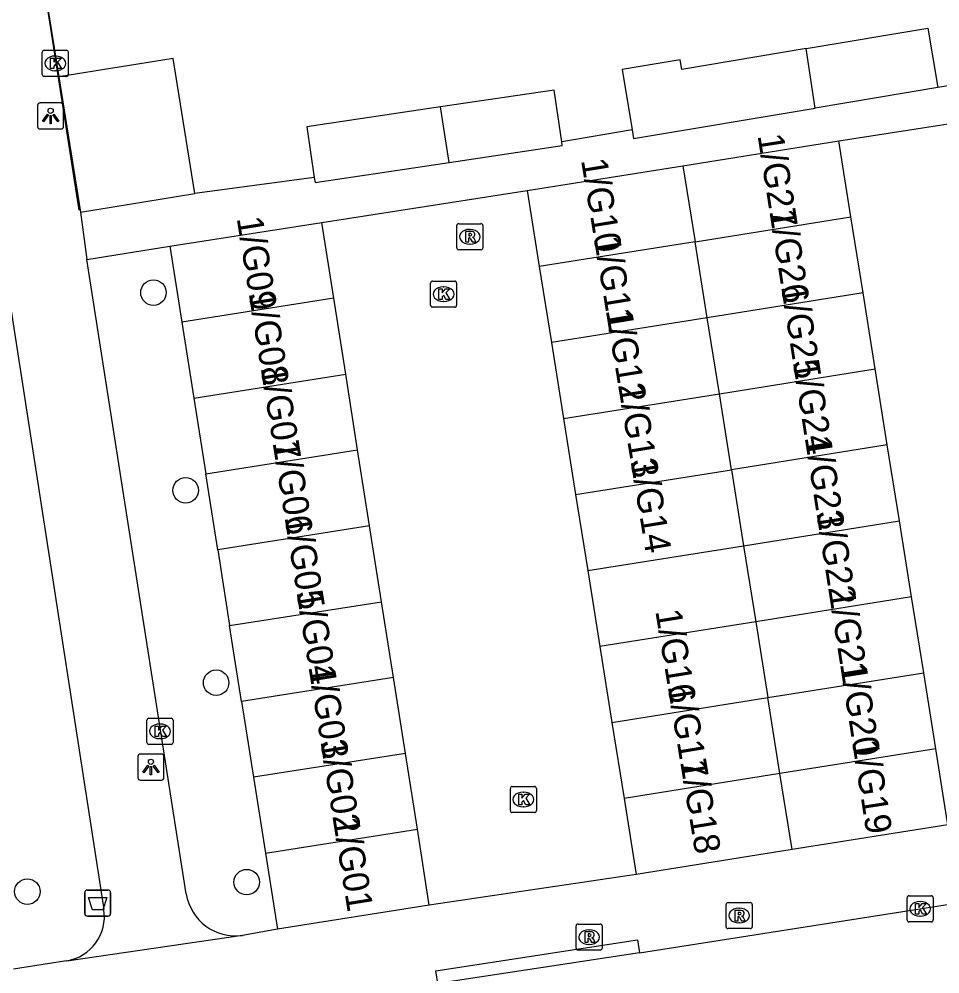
# Model space of a CAD drawing. Extents: x 160077 to 160945, y 386481 to 387498.
# Drawn here: x 160454.89 to 160490.18, y 387076.44 to 387113.04 of the extents above; entities that cross this region are included whole.
import ezdxf

# ---------------------------------------------------------------- set-up
doc = ezdxf.new("R2010")
doc.units = 0
for name, color, linetype in [('IMGEO_Afvalbak', 7, 'Continuous'), ('IMGEO_Boom', 7, 'Continuous'), ('IMGEO_Kolk', 7, 'Continuous'), ('IMGEO_Lichtpunt', 7, 'Continuous'), ('IMGEO_Muur', 7, 'Continuous'), ('IMGEO_Pand', 7, 'Continuous'), ('IMGEO_Pand_nummerreeks', 7, 'Continuous'), ('IMGEO_Rijbaan_lokaal_open', 7, 'Continuous'), ('IMGEO_Rioolput', 7, 'Continuous'), ('IMGEO_Voetpad_open', 7, 'Continuous')]:
    doc.layers.add(name, color=color, linetype=linetype)

msp = doc.modelspace()

# ---------------------------------------------------------------- linework, layer by layer
at = {"layer": 'IMGEO_Afvalbak'}
for p, q in [((160457.41, 387078.749), (160457.41, 387079.549)), ((160457.41, 387079.549), (160457.41, 387078.749)), ((160457.51, 387079.649), (160458.3, 387079.649)), ((160458.3, 387079.649), (160457.51, 387079.649)), ((160458.4, 387079.549), (160458.4, 387078.749)), ((160458.4, 387078.749), (160458.4, 387079.549)), ((160458.3, 387078.649), (160457.51, 387078.649)), ((160457.51, 387078.649), (160458.3, 387078.649))]:
    msp.add_line(p, q, dxfattribs=at)
msp.add_lwpolyline([(160457.553, 387079.363), (160458.257, 387079.363), (160458.108, 387078.893), (160457.702, 387078.893), (160457.553, 387079.363)], dxfattribs=at)
for centre, start, end in [((160457.51, 387079.549), 90, 180), ((160457.51, 387079.549), 90, 180), ((160458.3, 387079.549), 0, 90), ((160458.3, 387079.549), 360, 90), ((160457.51, 387078.749), 180, 270), ((160457.51, 387078.749), 180, 270), ((160458.3, 387078.749), 270, 0), ((160458.3, 387078.749), 270, 0)]:
    msp.add_arc(centre, 0.1, start, end, dxfattribs=at)
at = {"layer": 'IMGEO_Boom'}
for centre in [(160460.042, 387102.552), (160461.275, 387094.973), (160462.445, 387087.597), (160463.615, 387079.954), (160455.211, 387079.591)]:
    msp.add_circle(centre, 0.489, dxfattribs=at)
at = {"layer": 'IMGEO_Kolk'}
for p, q in [((160455.778, 387110.915), (160455.778, 387111.767)), ((160455.853, 387111.841), (160456.705, 387111.841)), ((160456.779, 387111.767), (160456.779, 387110.915)), ((160456.266, 387111.621), (160456.291, 387111.621)), ((160456.289, 387111.061), (160456.264, 387111.061)), ((160456.705, 387110.841), (160455.853, 387110.841)), ((160470.66, 387102.068), (160470.66, 387102.92)), ((160470.735, 387102.994), (160471.587, 387102.994)), ((160471.661, 387102.92), (160471.661, 387102.068)), ((160471.148, 387102.774), (160471.173, 387102.774)), ((160471.171, 387102.214), (160471.146, 387102.214)), ((160471.587, 387101.994), (160470.735, 387101.994)), ((160459.792, 387085.308), (160459.792, 387086.16)), ((160459.867, 387086.234), (160460.719, 387086.234)), ((160460.793, 387086.16), (160460.793, 387085.308)), ((160460.28, 387086.014), (160460.305, 387086.014)), ((160460.303, 387085.454), (160460.278, 387085.454)), ((160460.719, 387085.234), (160459.867, 387085.234)), ((160473.719, 387082.694), (160473.719, 387083.546)), ((160473.794, 387083.62), (160474.646, 387083.62)), ((160474.72, 387083.546), (160474.72, 387082.694)), ((160474.207, 387083.4), (160474.232, 387083.4)), ((160474.23, 387082.84), (160474.205, 387082.84)), ((160474.646, 387082.62), (160473.794, 387082.62)), ((160488.925, 387078.503), (160488.925, 387079.355)), ((160489, 387079.429), (160489.852, 387079.429)), ((160489.413, 387079.209), (160489.438, 387079.209)), ((160489.926, 387079.355), (160489.926, 387078.503)), ((160489.852, 387078.429), (160489, 387078.429)), ((160489.436, 387078.649), (160489.411, 387078.649))]:
    msp.add_line(p, q, dxfattribs=at)
for points in [[(160455.778, 387110.915), (160455.778, 387111.767)], [(160455.853, 387111.841), (160456.705, 387111.841)], [(160456.779, 387111.767), (160456.779, 387110.915)], [(160456.099, 387111.541), (160456.222, 387111.541), (160456.222, 387111.39), (160456.352, 387111.541), (160456.516, 387111.541), (160456.37, 387111.39), (160456.523, 387111.141), (160456.371, 387111.141), (160456.286, 387111.305), (160456.222, 387111.238), (160456.222, 387111.141), (160456.099, 387111.141), (160456.099, 387111.541)], [(160456.705, 387110.841), (160455.853, 387110.841)], [(160470.66, 387102.068), (160470.66, 387102.92)], [(160470.735, 387102.994), (160471.587, 387102.994)], [(160471.661, 387102.92), (160471.661, 387102.068)], [(160470.981, 387102.694), (160471.104, 387102.694), (160471.104, 387102.543), (160471.234, 387102.694), (160471.398, 387102.694), (160471.252, 387102.543), (160471.405, 387102.294), (160471.253, 387102.294), (160471.168, 387102.458), (160471.104, 387102.391), (160471.104, 387102.294), (160470.981, 387102.294), (160470.981, 387102.694)], [(160471.587, 387101.994), (160470.735, 387101.994)], [(160459.792, 387085.308), (160459.792, 387086.16)], [(160459.867, 387086.234), (160460.719, 387086.234)], [(160460.793, 387086.16), (160460.793, 387085.308)], [(160460.113, 387085.934), (160460.236, 387085.934), (160460.236, 387085.783), (160460.366, 387085.934), (160460.53, 387085.934), (160460.384, 387085.783), (160460.537, 387085.534), (160460.385, 387085.534), (160460.3, 387085.698), (160460.236, 387085.631), (160460.236, 387085.534), (160460.113, 387085.534), (160460.113, 387085.934)], [(160460.719, 387085.234), (160459.867, 387085.234)], [(160473.719, 387082.694), (160473.719, 387083.546)], [(160473.794, 387083.62), (160474.646, 387083.62)], [(160474.72, 387083.546), (160474.72, 387082.694)], [(160474.04, 387083.32), (160474.163, 387083.32), (160474.163, 387083.169), (160474.293, 387083.32), (160474.457, 387083.32), (160474.311, 387083.169), (160474.464, 387082.92), (160474.312, 387082.92), (160474.227, 387083.084), (160474.163, 387083.017), (160474.163, 387082.92), (160474.04, 387082.92), (160474.04, 387083.32)], [(160474.646, 387082.62), (160473.794, 387082.62)], [(160488.925, 387078.503), (160488.925, 387079.355)], [(160489, 387079.429), (160489.852, 387079.429)], [(160489.246, 387079.129), (160489.369, 387079.129), (160489.369, 387078.978), (160489.499, 387079.129), (160489.663, 387079.129), (160489.517, 387078.978), (160489.67, 387078.729), (160489.518, 387078.729), (160489.433, 387078.893), (160489.369, 387078.826), (160489.369, 387078.729), (160489.246, 387078.729), (160489.246, 387079.129)], [(160489.926, 387079.355), (160489.926, 387078.503)], [(160489.852, 387078.429), (160489, 387078.429)]]:
    msp.add_lwpolyline(points, dxfattribs=at)
for centre, start, end in [((160455.855, 387111.765), 91.552, 178.448), ((160455.855, 387111.765), 91.552, 178.448), ((160456.703, 387111.765), 1.552, 88.448), ((160456.703, 387111.765), 1.552, 88.448), ((160455.855, 387110.917), 181.552, 268.448), ((160455.855, 387110.917), 181.552, 268.448), ((160456.703, 387110.917), 271.552, 358.448), ((160456.703, 387110.917), 271.552, 358.448), ((160470.737, 387102.918), 91.552, 178.448), ((160470.737, 387102.918), 91.552, 178.448), ((160471.585, 387102.918), 1.552, 88.448), ((160471.585, 387102.918), 1.552, 88.448), ((160470.737, 387102.07), 181.552, 268.448), ((160470.737, 387102.07), 181.552, 268.448), ((160471.585, 387102.07), 271.552, 358.448), ((160471.585, 387102.07), 271.552, 358.448), ((160459.869, 387086.158), 91.552, 178.448), ((160459.869, 387086.158), 91.552, 178.448), ((160460.717, 387086.158), 1.552, 88.448), ((160460.717, 387086.158), 1.552, 88.448), ((160459.869, 387085.31), 181.552, 268.448), ((160459.869, 387085.31), 181.552, 268.448), ((160460.717, 387085.31), 271.552, 358.448), ((160460.717, 387085.31), 271.552, 358.448), ((160473.796, 387083.544), 91.552, 178.448), ((160473.796, 387083.544), 91.552, 178.448), ((160474.644, 387083.544), 1.552, 88.448), ((160474.644, 387083.544), 1.552, 88.448), ((160473.796, 387082.696), 181.552, 268.448), ((160473.796, 387082.696), 181.552, 268.448), ((160474.644, 387082.696), 271.552, 358.448), ((160474.644, 387082.696), 271.552, 358.448), ((160489.002, 387079.353), 91.552, 178.448), ((160489.002, 387079.353), 91.552, 178.448), ((160489.85, 387079.353), 1.552, 88.448), ((160489.85, 387079.353), 1.552, 88.448), ((160489.002, 387078.505), 181.552, 268.448), ((160489.002, 387078.505), 181.552, 268.448), ((160489.85, 387078.505), 271.552, 358.448), ((160489.85, 387078.505), 271.552, 358.448)]:
    msp.add_arc(centre, 0.0765, start, end, dxfattribs=at)
for centre, major_axis, ratio, start_param, end_param in [((160456.265, 387111.341), (-0.387, 0.002), 0.722429, 4.712389, 7.853982), ((160456.29, 387111.341), (-0.39, 0.002), 0.717154, 1.570796, 4.712389), ((160471.147, 387102.494), (-0.387, 0.002), 0.722429, 4.712389, 7.853982), ((160471.172, 387102.494), (-0.39, 0.002), 0.717154, 1.570796, 4.712389), ((160460.279, 387085.734), (-0.387, 0.002), 0.722429, 4.712389, 7.853982), ((160460.304, 387085.734), (-0.39, 0.002), 0.717154, 1.570796, 4.712389), ((160474.206, 387083.12), (-0.387, 0.002), 0.722429, 4.712389, 7.853982), ((160474.231, 387083.12), (-0.39, 0.002), 0.717154, 1.570796, 4.712389), ((160489.412, 387078.929), (-0.387, 0.002), 0.722429, 4.712389, 7.853982), ((160489.437, 387078.929), (-0.39, 0.002), 0.717154, 1.570796, 4.712389)]:
    msp.add_ellipse(centre, major_axis=major_axis, ratio=ratio, start_param=start_param, end_param=end_param, dxfattribs=at)
at = {"layer": 'IMGEO_Lichtpunt'}
for p, q in [((160455.602, 387109.727), (160455.602, 387108.92)), ((160455.602, 387109.727), (160455.602, 387108.92)), ((160456.504, 387109.822), (160455.696, 387109.822)), ((160456.504, 387109.822), (160455.696, 387109.822)), ((160456.598, 387108.92), (160456.598, 387109.727)), ((160456.598, 387108.92), (160456.598, 387109.727)), ((160455.696, 387108.826), (160456.504, 387108.826)), ((160455.696, 387108.826), (160456.504, 387108.826)), ((160459.446, 387084.768), (160459.446, 387083.961)), ((160459.446, 387084.768), (160459.446, 387083.961)), ((160460.348, 387084.863), (160459.54, 387084.863)), ((160460.348, 387084.863), (160459.54, 387084.863)), ((160460.442, 387083.961), (160460.442, 387084.768)), ((160460.442, 387083.961), (160460.442, 387084.768)), ((160459.54, 387083.867), (160460.348, 387083.867)), ((160459.54, 387083.867), (160460.348, 387083.867))]:
    msp.add_line(p, q, dxfattribs=at)
for points in [[(160455.976, 387109.391), (160456.015, 387109.363), (160455.827, 387109.101), (160455.789, 387109.128), (160455.976, 387109.391)], [(160456.078, 387109.343), (160456.125, 387109.343), (160456.125, 387109.021), (160456.078, 387109.021), (160456.078, 387109.343)], [(160456.188, 387109.363), (160456.226, 387109.39), (160456.413, 387109.128), (160456.374, 387109.1), (160456.188, 387109.363)], [(160459.82, 387084.432), (160459.859, 387084.404), (160459.671, 387084.142), (160459.633, 387084.169), (160459.82, 387084.432)], [(160459.922, 387084.384), (160459.969, 387084.384), (160459.969, 387084.062), (160459.922, 387084.062), (160459.922, 387084.384)], [(160460.032, 387084.404), (160460.07, 387084.431), (160460.257, 387084.169), (160460.218, 387084.141), (160460.032, 387084.404)]]:
    msp.add_lwpolyline(points, dxfattribs=at)
for centre in [(160456.101, 387109.525), (160459.945, 387084.566)]:
    msp.add_circle(centre, 0.0994, dxfattribs=at)
for centre, start, end in [((160455.696, 387109.727), 90, 180), ((160455.696, 387109.727), 90, 180), ((160456.504, 387109.727), 0, 90), ((160456.504, 387109.727), 0, 90), ((160455.696, 387108.92), 180, 270), ((160455.696, 387108.92), 180, 270), ((160456.504, 387108.92), 270, 0), ((160456.504, 387108.92), 270, 360), ((160459.54, 387084.768), 90, 180), ((160459.54, 387084.768), 90, 180), ((160460.348, 387084.768), 0, 90), ((160460.348, 387084.768), 0, 90), ((160459.54, 387083.961), 180, 270), ((160459.54, 387083.961), 180, 270), ((160460.348, 387083.961), 270, 0), ((160460.348, 387083.961), 270, 360)]:
    msp.add_arc(centre, 0.0946, start, end, dxfattribs=at)
at = {"layer": 'IMGEO_Muur'}
msp.add_lwpolyline([(160455.401, 387117.108), (160457.188, 387105.719)], dxfattribs=at)
at = {"layer": 'IMGEO_Pand'}
for points in [[(160485.056, 387111.907), (160489.722, 387112.69), (160490.104, 387110.412)], [(160485.056, 387111.907), (160480.292, 387111.109), (160480.229, 387111.481), (160478, 387111.107), (160478.389, 387108.79)], [(160485.408, 387109.624), (160485.056, 387111.907)], [(160461.633, 387106.348), (160460.797, 387111.529), (160456.412, 387110.822)], [(160456.412, 387110.822), (160457.248, 387105.64)], [(160475.689, 387108.336), (160475.393, 387110.319), (160471.041, 387109.67)], [(160490.104, 387110.412), (160485.408, 387109.624)], [(160471.041, 387109.67), (160465.917, 387108.905), (160466.206, 387106.971)], [(160471.369, 387107.541), (160471.041, 387109.67)], [(160478.389, 387108.79), (160478.445, 387108.457), (160485.408, 387109.624)], [(160480.336, 387107.416), (160486.309, 387108.368)], [(160486.773, 387105.455), (160486.309, 387108.368)], [(160471.369, 387107.541), (160475.711, 387108.19), (160475.689, 387108.336)], [(160466.206, 387106.971), (160466.235, 387106.775), (160471.369, 387107.541)], [(160474.364, 387106.464), (160480.336, 387107.416)], [(160480.336, 387107.416), (160480.801, 387104.503)], [(160457.248, 387105.64), (160461.633, 387106.348)], [(160474.364, 387106.464), (160474.829, 387103.551)], [(160480.801, 387104.503), (160486.773, 387105.455)], [(160487.238, 387102.542), (160486.773, 387105.455)], [(160460.673, 387104.328), (160466.494, 387105.244)], [(160466.952, 387102.336), (160466.494, 387105.244)], [(160480.801, 387104.503), (160474.829, 387103.551)], [(160481.265, 387101.59), (160480.801, 387104.503)], [(160460.673, 387104.328), (160461.131, 387101.42)], [(160474.829, 387103.551), (160475.293, 387100.638)], [(160487.238, 387102.542), (160481.265, 387101.59)], [(160487.702, 387099.629), (160487.238, 387102.542)], [(160466.952, 387102.336), (160461.131, 387101.42)], [(160467.409, 387099.428), (160466.952, 387102.336)], [(160461.131, 387101.42), (160461.588, 387098.512)], [(160481.265, 387101.59), (160475.293, 387100.638)], [(160481.729, 387098.677), (160481.265, 387101.59)], [(160475.293, 387100.638), (160475.757, 387097.725)], [(160481.729, 387098.677), (160487.702, 387099.629)], [(160488.167, 387096.716), (160487.702, 387099.629)], [(160461.588, 387098.512), (160467.409, 387099.428)], [(160467.867, 387096.52), (160467.409, 387099.428)], [(160461.588, 387098.512), (160462.046, 387095.604)], [(160475.757, 387097.725), (160481.729, 387098.677)], [(160482.194, 387095.764), (160481.729, 387098.677)], [(160475.757, 387097.725), (160476.222, 387094.812)], [(160488.167, 387096.716), (160482.194, 387095.764)], [(160488.631, 387093.804), (160488.167, 387096.716)], [(160462.046, 387095.604), (160467.867, 387096.52)], [(160468.325, 387093.612), (160467.867, 387096.52)], [(160462.504, 387092.696), (160462.046, 387095.604)], [(160476.222, 387094.812), (160482.194, 387095.764)], [(160482.194, 387095.764), (160482.658, 387092.851)], [(160476.222, 387094.812), (160476.686, 387091.899)], [(160482.658, 387092.851), (160488.631, 387093.804)], [(160489.096, 387090.891), (160488.631, 387093.804)], [(160468.325, 387093.612), (160462.504, 387092.696)], [(160468.782, 387090.704), (160468.325, 387093.612)], [(160462.504, 387092.696), (160462.961, 387089.788)], [(160476.686, 387091.899), (160482.658, 387092.851)], [(160482.658, 387092.851), (160483.122, 387089.938)], [(160476.686, 387091.899), (160477.151, 387088.986)], [(160489.096, 387090.891), (160483.122, 387089.938)], [(160489.56, 387087.978), (160489.096, 387090.891)], [(160462.961, 387089.788), (160468.782, 387090.704)], [(160469.24, 387087.796), (160468.782, 387090.704)], [(160463.419, 387086.88), (160462.961, 387089.788)], [(160483.122, 387089.938), (160477.151, 387088.986)], [(160483.122, 387089.938), (160483.587, 387087.025)], [(160477.151, 387088.986), (160477.615, 387086.073)], [(160483.587, 387087.025), (160489.56, 387087.978)], [(160490.025, 387085.065), (160489.56, 387087.978)], [(160469.24, 387087.796), (160463.419, 387086.88)], [(160469.698, 387084.888), (160469.24, 387087.796)], [(160463.419, 387086.88), (160463.877, 387083.972)], [(160477.615, 387086.073), (160483.587, 387087.025)], [(160484.051, 387084.112), (160483.587, 387087.025)], [(160477.615, 387086.073), (160478.08, 387083.16)], [(160490.025, 387085.065), (160484.051, 387084.112)], [(160490.489, 387082.152), (160490.025, 387085.065)], [(160469.698, 387084.888), (160463.877, 387083.972)], [(160470.155, 387081.98), (160469.698, 387084.888)], [(160463.877, 387083.972), (160464.334, 387081.064)], [(160484.051, 387084.112), (160478.08, 387083.16)], [(160484.515, 387081.199), (160484.051, 387084.112)], [(160478.08, 387083.16), (160478.544, 387080.247)], [(160490.489, 387082.152), (160484.515, 387081.199)], [(160464.334, 387081.064), (160470.155, 387081.98)], [(160470.613, 387079.072), (160470.155, 387081.98)], [(160464.334, 387081.064), (160464.792, 387078.156)], [(160484.515, 387081.199), (160478.544, 387080.247)], [(160470.613, 387079.072), (160464.792, 387078.156)]]:
    msp.add_lwpolyline(points, dxfattribs=at)
at = {"layer": 'IMGEO_Rijbaan_lokaal_open'}
for points in [[(160486.309, 387108.368), (160494.042, 387109.568)], [(160466.494, 387105.244), (160474.364, 387106.464)], [(160478.544, 387080.247), (160470.613, 387079.072)], [(160478.664, 387077.241), (160490.963, 387079.169)], [(160478.664, 387077.241), (160470.935, 387076.063)]]:
    msp.add_lwpolyline(points, dxfattribs=at)
at = {"layer": 'IMGEO_Rioolput'}
for p, q in [((160471.666, 387104.27), (160471.666, 387105.122)), ((160471.741, 387105.196), (160472.593, 387105.196)), ((160472.667, 387105.122), (160472.667, 387104.27)), ((160472.154, 387104.976), (160472.179, 387104.976)), ((160472.177, 387104.416), (160472.152, 387104.416)), ((160472.593, 387104.196), (160471.741, 387104.196)), ((160481.988, 387078.246), (160481.988, 387079.098)), ((160482.063, 387079.172), (160482.915, 387079.172)), ((160482.989, 387079.098), (160482.989, 387078.246)), ((160482.476, 387078.952), (160482.501, 387078.952)), ((160482.499, 387078.392), (160482.474, 387078.392)), ((160476.238, 387077.42), (160476.238, 387078.272)), ((160476.313, 387078.346), (160477.165, 387078.346)), ((160476.726, 387078.126), (160476.751, 387078.126)), ((160477.239, 387078.272), (160477.239, 387077.42)), ((160482.915, 387078.172), (160482.063, 387078.172)), ((160477.165, 387077.346), (160476.313, 387077.346)), ((160476.749, 387077.566), (160476.724, 387077.566))]:
    msp.add_line(p, q, dxfattribs=at)
for points in [[(160471.666, 387104.27), (160471.666, 387105.122)], [(160471.741, 387105.196), (160472.593, 387105.196)], [(160472.667, 387105.122), (160472.667, 387104.27)], [(160472.255, 387104.894), (160472.003, 387104.896), (160472.003, 387104.496)], [(160472.181, 387104.815), (160472.127, 387104.815), (160472.127, 387104.734)], [(160472.127, 387104.734), (160472.179, 387104.734)], [(160472.003, 387104.496), (160472.127, 387104.496), (160472.127, 387104.658), (160472.138, 387104.658)], [(160472.185, 387104.629), (160472.256, 387104.496), (160472.396, 387104.496), (160472.331, 387104.622)], [(160472.593, 387104.196), (160471.741, 387104.196)], [(160481.988, 387078.246), (160481.988, 387079.098)], [(160482.063, 387079.172), (160482.915, 387079.172)], [(160482.989, 387079.098), (160482.989, 387078.246)], [(160482.577, 387078.87), (160482.325, 387078.872), (160482.325, 387078.472)], [(160482.503, 387078.791), (160482.449, 387078.791), (160482.449, 387078.71)], [(160482.325, 387078.472), (160482.449, 387078.472), (160482.449, 387078.634), (160482.46, 387078.634)], [(160482.449, 387078.71), (160482.501, 387078.71)], [(160482.507, 387078.605), (160482.578, 387078.472), (160482.718, 387078.472), (160482.653, 387078.598)], [(160476.238, 387077.42), (160476.238, 387078.272)], [(160476.313, 387078.346), (160477.165, 387078.346)], [(160476.827, 387078.044), (160476.575, 387078.046), (160476.575, 387077.646)], [(160477.239, 387078.272), (160477.239, 387077.42)], [(160482.915, 387078.172), (160482.063, 387078.172)], [(160476.575, 387077.646), (160476.699, 387077.646), (160476.699, 387077.808), (160476.71, 387077.808)], [(160476.753, 387077.965), (160476.699, 387077.965), (160476.699, 387077.884)], [(160476.699, 387077.884), (160476.751, 387077.884)], [(160476.757, 387077.779), (160476.828, 387077.646), (160476.968, 387077.646), (160476.903, 387077.772)], [(160477.165, 387077.346), (160476.313, 387077.346)]]:
    msp.add_lwpolyline(points, dxfattribs=at)
for centre, radius, start, end in [((160471.743, 387105.12), 0.0765, 91.552, 178.448), ((160471.743, 387105.12), 0.0765, 91.552, 178.448), ((160472.591, 387105.12), 0.0765, 1.552, 88.448), ((160472.591, 387105.12), 0.0765, 1.552, 88.448), ((160472.163, 387104.923), 0.19, 274.7715, 282.9687), ((160472.187, 387104.719), 0.0964, 77.0061, 93.1865), ((160472.201, 387104.776), 0.0378, 276.6634, 79.6772), ((160472.254, 387104.784), 0.109, 350.3612, 89.416), ((160472.252, 387104.784), 0.112, 277.5842, 350.9817), ((160472.137, 387104.605), 0.0533, 26.0293, 88.6989), ((160472.236, 387104.569), 0.108, 29.5134, 73.7905), ((160471.743, 387104.272), 0.0765, 181.552, 268.448), ((160471.743, 387104.272), 0.0765, 181.552, 268.448), ((160472.591, 387104.272), 0.0765, 271.552, 358.448), ((160472.591, 387104.272), 0.0765, 271.552, 358.448), ((160482.065, 387079.096), 0.0765, 91.552, 178.448), ((160482.065, 387079.096), 0.0765, 91.552, 178.448), ((160482.913, 387079.096), 0.0765, 1.552, 88.448), ((160482.913, 387079.096), 0.0765, 1.552, 88.448), ((160482.485, 387078.899), 0.19, 274.7715, 282.9687), ((160482.509, 387078.695), 0.0964, 77.0061, 93.1865), ((160482.523, 387078.752), 0.0378, 276.6634, 79.6772), ((160482.576, 387078.76), 0.109, 350.3612, 89.416), ((160482.574, 387078.76), 0.112, 277.5842, 350.9817), ((160482.459, 387078.581), 0.0533, 26.0293, 88.6989), ((160482.558, 387078.545), 0.108, 29.5134, 73.7905), ((160476.315, 387078.27), 0.0765, 91.552, 178.448), ((160476.315, 387078.27), 0.0765, 91.552, 178.448), ((160476.826, 387077.934), 0.109, 350.3612, 89.416), ((160477.163, 387078.27), 0.0765, 1.552, 88.448), ((160477.163, 387078.27), 0.0765, 1.552, 88.448), ((160482.065, 387078.248), 0.0765, 181.552, 268.448), ((160482.065, 387078.248), 0.0765, 181.552, 268.448), ((160482.913, 387078.248), 0.0765, 271.552, 358.448), ((160482.913, 387078.248), 0.0765, 271.552, 358.448), ((160476.709, 387077.755), 0.0533, 26.0293, 88.6989), ((160476.735, 387078.073), 0.19, 274.7715, 282.9687), ((160476.759, 387077.869), 0.0964, 77.0061, 93.1865), ((160476.773, 387077.926), 0.0378, 276.6634, 79.6772), ((160476.824, 387077.934), 0.112, 277.5842, 350.9817), ((160476.808, 387077.719), 0.108, 29.5134, 73.7905), ((160476.315, 387077.422), 0.0765, 181.552, 268.448), ((160476.315, 387077.422), 0.0765, 181.552, 268.448), ((160477.163, 387077.422), 0.0765, 271.552, 358.448), ((160477.163, 387077.422), 0.0765, 271.552, 358.448)]:
    msp.add_arc(centre, radius, start, end, dxfattribs=at)
for centre, major_axis, ratio, start_param, end_param in [((160472.153, 387104.696), (-0.387, 0.002), 0.722429, 4.712389, 7.853982), ((160472.178, 387104.696), (-0.39, 0.002), 0.717154, 1.570796, 4.712389), ((160482.475, 387078.672), (-0.387, 0.002), 0.722429, 4.712389, 7.853982), ((160482.5, 387078.672), (-0.39, 0.002), 0.717154, 1.570796, 4.712389), ((160476.725, 387077.846), (-0.387, 0.002), 0.722429, 4.712389, 7.853982), ((160476.75, 387077.846), (-0.39, 0.002), 0.717154, 1.570796, 4.712389)]:
    msp.add_ellipse(centre, major_axis=major_axis, ratio=ratio, start_param=start_param, end_param=end_param, dxfattribs=at)
at = {"layer": 'IMGEO_Voetpad_open'}
for points in [[(160454.971, 387119.846), (160455.401, 387117.108), (160456.412, 387110.822)], [(160494.296, 387111.102), (160490.104, 387110.412)], [(160478.389, 387108.79), (160475.689, 387108.336)], [(160466.206, 387106.971), (160461.633, 387106.348)], [(160454.011, 387105.484), (160458.14, 387078.907)], [(160457.248, 387105.64), (160457.484, 387103.826)], [(160457.484, 387103.826), (160460.673, 387104.328)], [(160461.299, 387079.505), (160457.484, 387103.826)], [(160464.792, 387078.156), (160463.451, 387077.912)], [(160463.451, 387077.912), (160463.45, 387077.906), (160456.718, 387076.923), (160456.708, 387076.935)], [(160470.935, 387076.063), (160470.86, 387076.557), (160478.589, 387077.735), (160478.664, 387077.241)], [(160456.708, 387076.935), (160454.682, 387076.62)]]:
    msp.add_lwpolyline(points, dxfattribs=at)
for centre, radius, start, end in [((160463.191, 387079.81), 1.916, 189.1711, 277.8081), ((160456.434, 387078.64), 1.727, 279.1332, 8.895)]:
    msp.add_arc(centre, radius, start, end, dxfattribs=at)

# ---------------------------------------------------------------- texts
at = {"layer": 'IMGEO_Pand_nummerreeks'}
for s, rotation, p in [('1/G27', 278.8667, (160483.192, 387108.577)), ('1/G10', 279.3503, (160476.427, 387107.631)), ('1/G26', 278.8667, (160483.643, 387105.684)), ('1/G09', 279.0903, (160463.229, 387105.404)), ('1/G11', 279.3503, (160476.919, 387104.644)), ('1/G08', 279.0903, (160463.689, 387102.533)), ('1/G25', 278.8667, (160484.095, 387102.79)), ('1/G12', 279.3503, (160477.374, 387101.877)), ('1/G07', 279.0903, (160464.147, 387099.672)), ('1/G24', 278.8667, (160484.546, 387099.897)), ('1/G13', 279.3503, (160477.85, 387098.988)), ('1/G06', 279.0903, (160464.605, 387096.807)), ('1/G23', 278.8667, (160484.997, 387097.003)), ('1/G14', 279.3503, (160478.324, 387096.106)), ('1/G22', 278.8667, (160485.448, 387094.116)), ('1/G05', 279.0903, (160465.063, 387093.942)), ('1/G04', 279.0903, (160465.522, 387091.078)), ('1/G21', 278.8667, (160485.917, 387091.107)), ('1/G16', 279.3503, (160479.273, 387090.343)), ('1/G20', 278.8667, (160486.352, 387088.32)), ('1/G03', 279.0903, (160465.98, 387088.213)), ('1/G17', 279.3503, (160479.748, 387087.461)), ('1/G02', 279.0903, (160466.437, 387085.355)), ('1/G19', 278.8667, (160486.816, 387085.342)), ('1/G18', 279.3503, (160480.223, 387084.576)), ('1/G01', 279.0903, (160466.914, 387082.375))]:
    msp.add_text(s, height=1, rotation=rotation, dxfattribs=at).set_placement(p)

doc.saveas('drawing.dxf')
